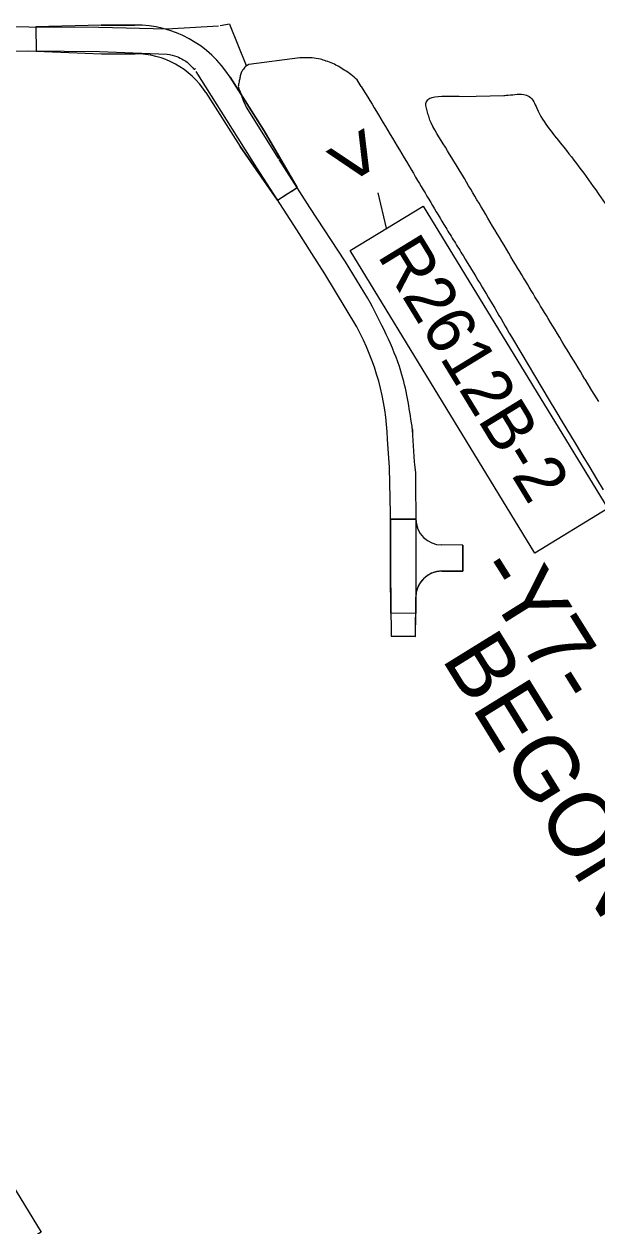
# Model space of a CAD drawing. Extents: x 1771071 to 1790027, y 804210 to 823391.
# Drawn here: x 1780140 to 1780578, y 814798 to 815717 of the extents above; entities that cross this region are included whole.
import ezdxf

# ---------------------------------------------------------------- set-up
doc = ezdxf.new("R2010")
doc.units = 0
for name, color, linetype in [('Default', 7, 'Continuous'), ('Exist Roads EOP', 7, 'Continuous'), ('Old_Level_57', 7, 'Continuous'), ('Prop Conc 5in Monolithic Surface Mount Island', 7, 'Continuous'), ('Proposed Right of Way Monument PSD Text', 7, 'Continuous'), ('Scratch_Level_7', 7, 'Continuous'), ('Scratch_Level_8', 7, 'Continuous')]:
    doc.layers.add(name, color=color, linetype=linetype)

msp = doc.modelspace()

# ---------------------------------------------------------------- linework, layer by layer
at = {"layer": 'Default'}
msp.add_lwpolyline([(1780417.12, 815560.98), (1780417.12, 815560.98), (1780410.69, 815587.96)], dxfattribs=at)
for points in [[(1780444.98, 815578), (1780586.31, 815346.68), (1780530.59, 815312.64), (1780389.26, 815543.95)], [(1780048.64, 814964.02), (1780152.76, 814793.61), (1780080.64, 814749.55), (1779976.52, 814919.95)]]:
    msp.add_lwpolyline(points, close=True, dxfattribs=at)
at = {"layer": 'Exist Roads EOP'}
for p, q in [((1780289.83, 815715.97), (1780297, 815717.19)), ((1780296.95, 815717.03), (1780309.74, 815685.34)), ((1780311.8, 815686.14), (1780309.21, 815684.77)), ((1780350.72, 815691.25), (1780311.8, 815686.14)), ((1780270.45, 815683.16), (1780270.83, 815682.74)), ((1780397.65, 815669.47), (1780394.55, 815674.49)), ((1780475.21, 815661.76), (1780506.7, 815662.57)), ((1780514.13, 815475.41), (1780541.51, 815429.53)), ((1780419.38, 815378.01), (1780417.79, 815399.89))]:
    msp.add_line(p, q, dxfattribs=at)
for points in [[(1780089.57, 815715.2), (1780143.52, 815714.96), (1780196.9, 815714.8), (1780248.96, 815713.54), (1780288.49, 815715.72)], [(1780089.54, 815696.41), (1780143.4, 815696.53), (1780197.37, 815696.05), (1780249.15, 815694.02)], [(1780394.31, 815485.55), (1780369.81, 815526.12), (1780359.87, 815541.71), (1780348.41, 815559.68), (1780317.78, 815607.22), (1780294.87, 815643.72), (1780271.56, 815680.72)], [(1780309.72, 815653.68), (1780333.23, 815616.01), (1780334.39, 815614.14)], [(1780402.62, 815507.79), (1780385.7, 815535.39), (1780358.45, 815576.96), (1780334.89, 815613.54)], [(1780568.83, 815445.75), (1780573.98, 815436.97), (1780579.15, 815428.58)], [(1780541.51, 815429.53), (1780546.53, 815421.28), (1780552.15, 815411.85), (1780557.14, 815403.75), (1780562.22, 815395.37), (1780567.28, 815386.77), (1780572.5, 815378.09), (1780577.56, 815369.58), (1780582.71, 815361.12)], [(1780439.11, 815374.16), (1780439.55, 815330.21), (1780439.38, 815266.42), (1780420.4, 815266.68), (1780420.03, 815298.67), (1780420.2, 815342.77), (1780419.38, 815378.01)]]:
    msp.add_lwpolyline(points, dxfattribs=at)
for centre, major_axis, ratio, start_param, end_param in [((1780225.51, 815393.28), (175.12, -79.67), 0.999841, 0.461351, 0.927272), ((1780792.19, 815414.35), (-16.01, -356.92), 0.99448, 4.777349, 4.86968)]:
    msp.add_ellipse(centre, major_axis=major_axis, ratio=ratio, start_param=start_param, end_param=end_param, dxfattribs=at)
for points in [[(1780249.15, 815694.02), (1780256.73, 815692.24), (1780261.48, 815689.79), (1780265.63, 815686.96), (1780270.45, 815683.13), (1780270.45, 815683.16)], [(1780394.55, 815674.49), (1780389.83, 815678.6), (1780385.07, 815681.72), (1780380.57, 815684.53), (1780375.96, 815686.89), (1780370.85, 815688.81), (1780366.44, 815690.2), (1780360.2, 815691.22), (1780350.72, 815691.25)], [(1780309.21, 815684.77), (1780306.99, 815681.84), (1780305.55, 815679.11), (1780304.9, 815676.08), (1780304.23, 815672.91), (1780303.69, 815669.34), (1780303.75, 815668.45), (1780304.54, 815666.57), (1780306.48, 815661.37), (1780309.72, 815653.68)], [(1780397.65, 815669.47), (1780410.92, 815647.62), (1780439.35, 815600.02), (1780462.39, 815561.57), (1780468.94, 815550.84), (1780475.57, 815540.15), (1780488.65, 815518.69), (1780514.13, 815475.41)], [(1780568.83, 815445.75), (1780540.78, 815491.92), (1780517.58, 815530.32), (1780489.41, 815577.46), (1780463.71, 815620.24), (1780451.15, 815641.59), (1780450.24, 815643.55), (1780449.58, 815645.62), (1780449.03, 815647.73), (1780448.48, 815649.83), (1780447.86, 815651.78), (1780447.28, 815653.78), (1780447.08, 815655.77), (1780447.21, 815656.75), (1780447.35, 815657.24), (1780447.55, 815657.71), (1780450.24, 815660.4), (1780453.92, 815661.37), (1780475.21, 815661.76)], [(1780506.7, 815662.57), (1780508.51, 815662.62), (1780522.01, 815663.25), (1780526.24, 815661.69), (1780532, 815652.69), (1780552.77, 815622.87), (1780582.54, 815582.57), (1780612.44, 815541.29), (1780642.65, 815499.84), (1780667.85, 815459.72), (1780694.75, 815417.2), (1780723.52, 815371.6), (1780749.42, 815330.02), (1780774.91, 815289.68), (1780802.46, 815246.61), (1780830.98, 815200.79), (1780854.33, 815163.17), (1780881.32, 815120.56), (1780909.65, 815075.49), (1780935.09, 815035.08), (1780962.55, 814991.44), (1780988.57, 814949.94), (1781014.37, 814909.04), (1781040.71, 814867.19), (1781067.78, 814824.42), (1781096.04, 814779.44), (1781125.21, 814733.43), (1781151.13, 814691.5), (1781176.13, 814651.69), (1781204.54, 814606.64), (1781230.22, 814566), (1781256.12, 814524.87), (1781282.05, 814483.33), (1781310.29, 814438.62), (1781335.31, 814399.09), (1781361.83, 814356.7), (1781382.81, 814322.4), (1781389.52, 814309.42), (1781392.1, 814297.89), (1781391.6, 814294.95)], [(1780437, 815405.04), (1780436.77, 815408.32), (1780436.56, 815409.75), (1780428.12, 815451.64), (1780416.85, 815479.71), (1780402.62, 815507.79)]]:
    msp.add_spline(points, degree=3, dxfattribs=at)
at = {"layer": 'Prop Conc 5in Monolithic Surface Mount Island'}
for p, q in [((1780198.87, 815716.31), (1780148.87, 815714.94)), ((1780148.87, 815714.94), (1780148.92, 815696.38)), ((1780198.87, 815716.31), (1780224.6, 815716.37)), ((1780215.88, 815716.35), (1780224.6, 815716.37)), ((1780148.92, 815696.48), (1780198.92, 815694.31)), ((1780198.92, 815694.31), (1780224.65, 815694.37)), ((1780215.93, 815694.35), (1780224.65, 815694.37)), ((1780297.35, 815676.55), (1780323.56, 815635.39)), ((1780278.79, 815664.74), (1780305, 815623.57)), ((1780323.56, 815635.39), (1780348.69, 815592.11)), ((1780333.68, 815582.55), (1780305, 815623.57)), ((1780333.68, 815582.56), (1780348.69, 815592.11)), ((1780341.13, 815587.3), (1780345.35, 815589.99)), ((1780420.03, 815298.67), (1780420.18, 815338.51)), ((1780420.18, 815338.51), (1780439.47, 815338.7)), ((1780439.47, 815338.7), (1780439.46, 815339)), ((1780475.42, 815318.82), (1780459.36, 815318.9)), ((1780475.42, 815318.82), (1780475.32, 815298.82)), ((1780420.03, 815298.67), (1780420.6, 815249.1)), ((1780475.32, 815298.82), (1780459.26, 815298.9)), ((1780439.33, 815249), (1780439.41, 815278.95)), ((1780439.38, 815266.42), (1780439.39, 815268.95)), ((1780439.33, 815249), (1780420.6, 815249.1))]:
    msp.add_line(p, q, dxfattribs=at)
for centre in [(1780475.48, 815312.23), (1780475.48, 815304.23)]:
    msp.add_circle(centre, 0.0417, dxfattribs=at)
for centre, radius, start, end in [((1780224.8, 815630.37), 86, 32.48294, 90.13511), ((1780224.8, 815630.37), 64, 32.48294, 90.13511), ((1780459.46, 815338.9), 20, 180.56673, 269.69983), ((1780459.41, 815278.9), 20, 89.69983, 179.84849)]:
    msp.add_arc(centre, radius, start, end, dxfattribs=at)
at = {"layer": 'Scratch_Level_8'}
for p, q in [((1780198.87, 815716.31), (1780148.87, 815714.94)), ((1780148.87, 815714.94), (1780148.92, 815696.48)), ((1780148.92, 815696.48), (1780198.92, 815694.31)), ((1780198.92, 815694.31), (1780215.93, 815694.35)), ((1780215.93, 815694.35), (1780224.65, 815694.37)), ((1780323.56, 815635.39), (1780297.35, 815676.55)), ((1780278.79, 815664.74), (1780305, 815623.57)), ((1780348.69, 815592.11), (1780323.56, 815635.39)), ((1780305, 815623.57), (1780333.68, 815582.56)), ((1780333.68, 815582.56), (1780341.13, 815587.3)), ((1780341.13, 815587.3), (1780345.35, 815589.99)), ((1780345.35, 815589.99), (1780348.69, 815592.11)), ((1780420.18, 815338.51), (1780420.03, 815298.67)), ((1780439.47, 815338.7), (1780420.18, 815338.51)), ((1780475.42, 815318.82), (1780459.36, 815318.9)), ((1780475.32, 815298.82), (1780475.42, 815318.82)), ((1780420.03, 815298.67), (1780420.6, 815249.1)), ((1780439.39, 815268.95), (1780439.41, 815278.95)), ((1780439.33, 815249), (1780439.38, 815266.42)), ((1780439.38, 815266.42), (1780439.39, 815268.95)), ((1780420.6, 815249.1), (1780439.33, 815249))]:
    msp.add_line(p, q, dxfattribs=at)
for points in [[(1780224.6, 815716.37), (1780215.88, 815716.35), (1780198.87, 815716.31)], [(1780459.26, 815298.9), (1780459.26, 815298.9)], [(1780459.26, 815298.9), (1780459.52, 815298.9), (1780475.32, 815298.82)]]:
    msp.add_lwpolyline(points, dxfattribs=at)
for centre, radius, start, end in [((1780224.8, 815630.37), 86, 32.48294, 90.13511), ((1780224.8, 815630.37), 64, 32.48294, 90.13511), ((1780459.46, 815338.9), 20, 180.56673, 269.69983), ((1780459.41, 815278.9), 20, 90.45514, 179.84849)]:
    msp.add_arc(centre, radius, start, end, dxfattribs=at)

# ---------------------------------------------------------------- texts
at = {"layer": 'Old_Level_57'}
msp.add_text('>', height=46.95, rotation=301.43915, dxfattribs=at).set_placement((1780364.34, 815619.52))
at = {"layer": 'Proposed Right of Way Monument PSD Text'}
msp.add_text('R2612B-2', height=37.325, rotation=301.42495, dxfattribs=at).set_placement((1780409.56, 815540.24))
at = {"layer": 'Scratch_Level_7'}
for s, height, rotation, p in [('-Y7-', 49.208, 302.09437, (1780483.56, 815299.75)), ('BEGONIA DR.', 49.2075, 301.70956, (1780458.63, 815232.17))]:
    msp.add_text(s, height=height, rotation=rotation, dxfattribs=at).set_placement(p)

doc.saveas('drawing.dxf')
